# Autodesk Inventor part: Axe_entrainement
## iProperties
Shininess: 64.0
Length Units: 11269
Angle Units: 11279
Time Units: 11290
Mass Units: 11283
Length Display Precision: 3
Angle Display Precision: 2
Compacted: True
Part Number: Axe_entrainement
Document SubType Name: Modeling
Created: 2008-03
Material: Acier inoxydable, austénitique
Designer: Pascal
Density: 0.0
Volumn: 0.0
Area: 0.0
PropertySet Name: Model Information
Control State: 0
Master: False
Checked Out: False
DESIGNATION: pièce
Author: Pascal
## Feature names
1. Extrusion1
2. Chanfrein1 [Chamfer]
3. Extrusion2
4. Chanfrein2 [Chamfer]
5. Extrusion3
6. Extrusion4
7. Révolution1 [Revolution]
8. Congé1 [Fillet]
9. Extrusion5
10. Extrusion6
11. Chanfrein3 [Chamfer]
